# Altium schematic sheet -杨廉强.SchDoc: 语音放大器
size A4; Organization: 江门职业技术学院; Address1: 14电路1班; Address2: 杨廉强; Address3: 学号141806047; Address4: 语音放大器原理图; SheetNumber: 1; SheetTotal: 1
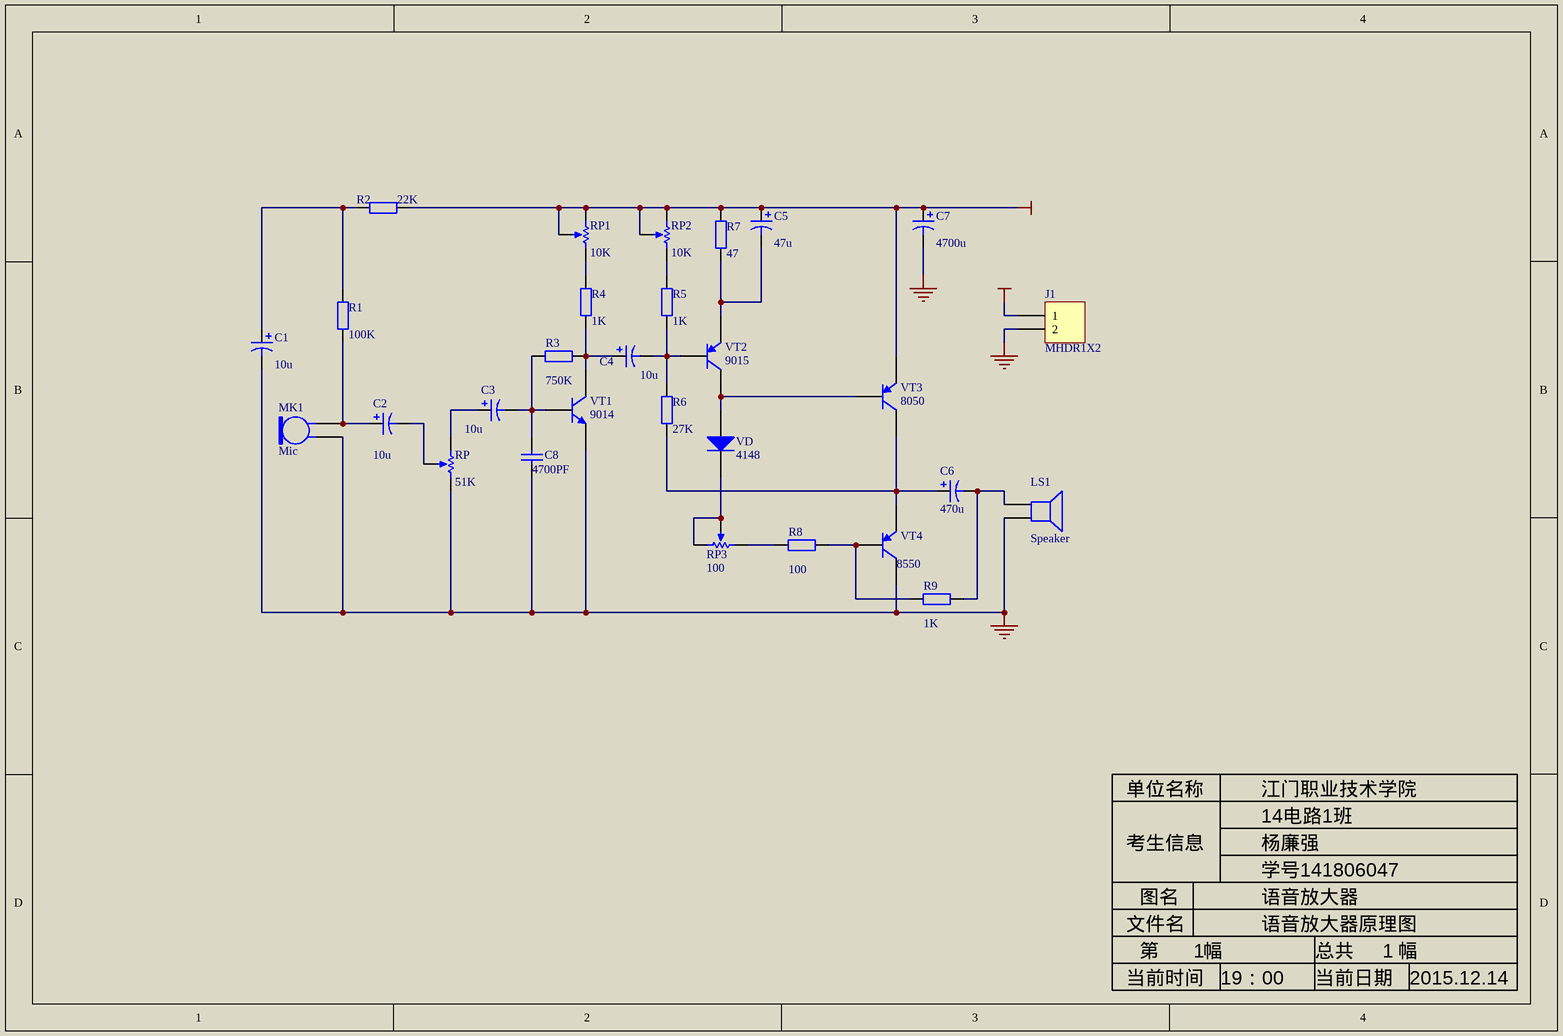
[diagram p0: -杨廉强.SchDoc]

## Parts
C1  value 10u  [CAPPR2-5x6.8]  (hidden comment: Cap Pol1)
C2  value 10u  [CAPPR2-5x6.8]  (hidden comment: Cap Pol1)
C3  value 10u  [CAPPR2-5x6.8]  (hidden comment: Cap Pol1)
C4  value 10u  [CAPPR2-5x6.8]  (hidden comment: Cap Pol1)
C5  value 47u  [CAPPR2-5x6.8]  (hidden comment: Cap Pol1)
C6  value 470u  [CAPPR5-5x5]  (hidden comment: Cap Pol1)
C7  value 4700u  [CAPPR5-5x5]  (hidden comment: Cap Pol1)
C8  value 4700PF  [CAPR2.54-5.1x3.2]  (hidden comment: Cap)
J1  MHDR1X2  [HDR1X2]
LS1  Speaker  [PIN2]
MK1  Mic  [PIN2]
R1  value 100K  [AXIAL-0.4]  (hidden comment: Res2)
R2  value 22K  [AXIAL-0.4]  (hidden comment: Res2)
R3  value 750K  [AXIAL-0.4]  (hidden comment: Res2)
R4  value 1K  [AXIAL-0.4]  (hidden comment: Res2)
R5  value 1K  [AXIAL-0.4]  (hidden comment: Res2)
R6  value 27K  [AXIAL-0.4]  (hidden comment: Res2)
R7  value 47  [AXIAL-0.4]  (hidden comment: Res2)
R8  value 100  [AXIAL-0.4]  (hidden comment: Res2)
R9  value 1K  [AXIAL-0.4]  (hidden comment: Res2)
RP  value 51K  [RM065]  (hidden comment: RPot)
RP1  value 10K  [RM065]  (hidden comment: RPot)
RP2  value 10K  [RM065]  (hidden comment: RPot)
RP3  value 100  [RM065]  (hidden comment: RPot)
VD  4148  [DIO7.1-3.9x1.9]
VT1  9014  [BCY-W3]
VT2  9015  [BCY-W3/E4]
VT3  8050  [BCY-W3/E4]
VT4  8550  [BCY-W3/E4]

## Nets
GND: C1.2 C7.2 C8.1 J1.2 LS1.2 MK1.1 RP.3(BOT) VT1.3(E) VT4.3(C)
VCC: C5.1 C7.1 J1.1 R2.1 R7.1 RP1.1(TOP) RP1.2(TAP) RP2.1(TOP) RP2.2(TAP) VT3.1(E)
NetC1_1: C1.1 R1.2 R2.2
NetC2_1: C2.1 MK1.2 R1.1
NetC2_2: C2.2 RP.2(TAP)
NetC3_1: C3.1 RP.1(TOP)
NetC3_2: C3.2 C8.2 R3.2 VT1.2(B)
NetC4_1: C4.1 R3.1 R4.2 VT1.1(C)
NetC4_2: C4.2 R5.2 R6.1 VT2.2(B)
NetC5_2: C5.2 R7.2 VT2.1(E)
NetC6_1: C6.1 R6.2 VT3.3(C) VT4.1(E)
NetC6_2: C6.2 LS1.1 R9.2
NetR4_1: R4.1 RP1.3(BOT)
NetR5_1: R5.1 RP2.3(BOT)
NetR8_1: R8.1 RP3.1(TOP)
NetR8_2: R8.2 R9.1 VT4.2(B)
NetRP3_2: RP3.2(TAP) RP3.3(BOT) VD.2(K)
NetVD_1: VD.1(A) VT2.3(C) VT3.2(B)

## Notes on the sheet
- 单位名称
- 考生信息
- 图名
- 文件名
- 当前时间
- 第        幅
- 当前日期
- 总共        幅

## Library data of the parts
C1-C7 = Cap Pol1: Polarized Capacitor (Radial)
C8 = Cap: Capacitor
J1 = Header 2: Header, 2-Pin
LS1 = Speaker: Loudspeaker
MK1 = Mic2: Microphone
R1-R9 = Res2: Resistor
RP RP1-RP3 = RPot: Potentiometer; Sim Note: Enter the Resistance value and the set point into parameter fields.; Set Position: 0.5
VD = Diode 1N4148: High Conductance Fast Diode
VT1 = NPN: NPN Bipolar Transistor
VT2-VT4 = 2N3906: PNP General Purpose Amplifier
